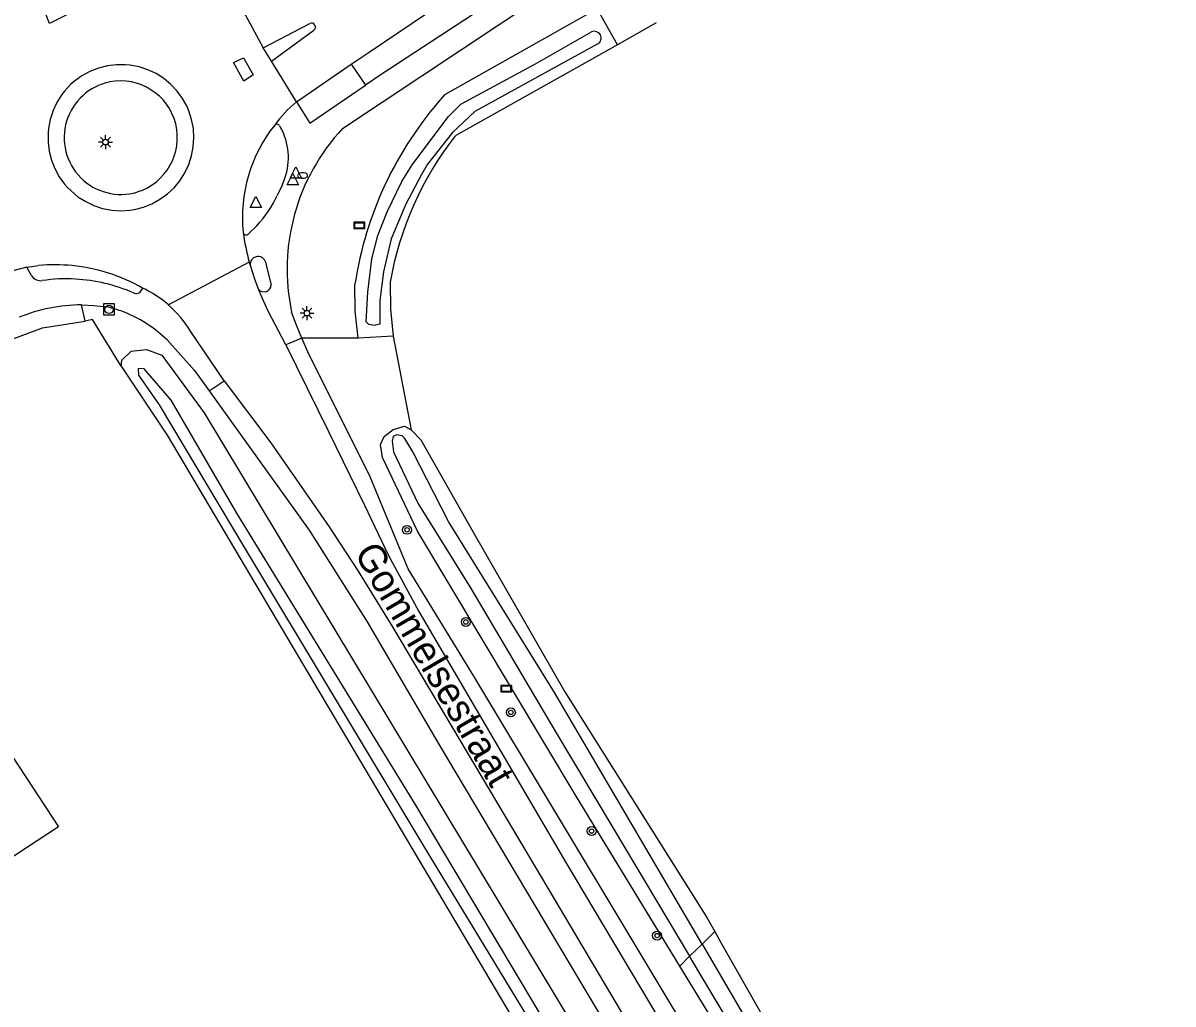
# Model space of a CAD drawing. Extents: x 137000 to 140001, y 403500 to 406000.
# Drawn here: x 139544.4 to 139647.6, y 403830.5 to 403918.5 of the extents above; entities that cross this region are included whole.
import ezdxf

# ---------------------------------------------------------------- set-up
doc = ezdxf.new("R2010")
doc.units = 0
for name, color, linetype in [('gg-anno-openbare ruimte label', 7, 'Continuous'), ('gg-bbg-hoofdgebouw', 7, 'Continuous'), ('gg-knt-bronhoudergrens', 7, 'Continuous'), ('gg-knt-verharding', 7, 'Continuous'), ('gg-knt-verharding nz', 7, 'Continuous'), ('gg-kntw-bovenkant insteek waterloop', 7, 'Continuous'), ('gg-kntw-waterlijn', 7, 'Continuous'), ('gt-grn-groengrens', 7, 'Continuous'), ('gt-grn-groengrens NZ', 7, 'Continuous'), ('gt-grn-vlakafsluiter', 7, 'Continuous'), ('gt-grn-weggrens', 7, 'Continuous'), ('gt-symb-boom', 7, 'Continuous'), ('gt-symb-brandkraan', 7, 'Continuous'), ('gt-symb-informatiebord', 7, 'Continuous'), ('gt-symb-lichtmast', 7, 'Continuous'), ('gt-symb-rioolschacht', 7, 'Continuous'), ('gt-symb-waterafsluiter', 7, 'Continuous')]:
    doc.layers.add(name, color=color, linetype=linetype)

# ---------------------------------------------------------------- blocks, each defined once
blk = doc.blocks.new('gt0-LMAST')
at = {"layer": 'gt-symb-lichtmast'}
for p, q in [((-0.18, 0.17), (-0.45, 0.44)), ((-0.01, 0.25), (-0.01, 0.62)), ((0.17, 0.17), (0.44, 0.44)), ((-0.26, 0), (-0.63, 0)), ((-0.18, -0.18), (-0.45, -0.45)), ((-0.01, -0.25), (-0.01, -0.63)), ((0.44, -0.45), (0.17, -0.18)), ((0.24, 0), (0.62, 0))]:
    blk.add_line(p, q, dxfattribs=at)
blk.add_circle((-0.01, 0), 0.25, dxfattribs=at)
blk = doc.blocks.new('gt0-WAFSL')
at = {"layer": 'gt-symb-waterafsluiter'}
for p, q in [((-0.5, -0.33), (0, 0.67)), ((0, 0.67), (0.5, -0.33)), ((0.5, -0.33), (-0.5, -0.33))]:
    blk.add_line(p, q, dxfattribs=at)
blk = doc.blocks.new('gt0-BR')
at = {"layer": 'gt-symb-brandkraan'}
for centre, radius, start, end in [((-0.24, 0), 0.206, 107.5669, 252.4331), ((0.6, -2.66), 3, 106.892, 107.5669), ((0, -0.69), 0.938, 73.108, 106.892), ((-0.6, -2.66), 3, 72.4331, 73.108), ((0.24, 0), 0.206, 287.567, 72.4331), ((0.6, 2.66), 3, 252.4331, 253.108), ((0, 0.69), 0.938, 253.108, 286.8921), ((-0.6, 2.66), 3, 286.8921, 287.567)]:
    blk.add_arc(centre, radius, start, end, dxfattribs=at)
blk = doc.blocks.new('gt0-IBORD')
at = {"layer": 'gt-symb-informatiebord'}
blk.add_lwpolyline([(-0.5, 0.29), (-0.5, -0.29), (0.5, -0.29), (0.5, 0.29), (-0.5, 0.29)], dxfattribs=at)
blk.add_lwpolyline([(-0.42, -0.21), (0.42, -0.21), (0.42, 0.21), (-0.42, 0.21)], close=True, dxfattribs=at)
blk = doc.blocks.new('gt0-RS')
at = {"layer": 'gt-symb-rioolschacht'}
blk.add_lwpolyline([(-0.5, -0.5), (0.5, -0.5), (0.5, 0.5), (-0.5, 0.5)], close=True, dxfattribs=at)
blk.add_circle((0, 0), 0.375, dxfattribs=at)
blk = doc.blocks.new('gt0-BOOM')
at = {"layer": 'gt-symb-boom'}
for radius in [0.4, 0.2]:
    blk.add_circle((0, 0), radius, dxfattribs=at)

msp = doc.modelspace()

# ---------------------------------------------------------------- linework, layer by layer
at = {"layer": 'gg-bbg-hoofdgebouw'}
msp.add_lwpolyline([(139526.12, 403841.26), (139543.52, 403852.68), (139547.62, 403846.42), (139530.21, 403835), (139526.12, 403841.26)], dxfattribs=at)
at = {"layer": 'gg-knt-bronhoudergrens'}
for p, q in [((139601.24, 403918.51), (139597.76, 403916.55)), ((139577.65, 403890.41), (139579.26, 403882.02))]:
    msp.add_line(p, q, dxfattribs=at)
msp.add_lwpolyline([(139553.26, 403887.72), (139550.69, 403891.91), (139550.03, 403891.77)], dxfattribs=at)
at = {"layer": 'gg-knt-verharding'}
for p, q in [((139573.1, 403909.05), (139593.34, 403922.49)), ((139565.99, 403916.28), (139570.17, 403918.45)), ((139566.73, 403915.07), (139570.54, 403917.85)), ((139566.73, 403915.07), (139565.99, 403916.28)), ((139568.97, 403911.43), (139573.88, 403914.8)), ((139573.88, 403914.8), (139575.17, 403912.92)), ((139567.46, 403909.27), (139567.8, 403908.62)), ((139567.71, 403904.03), (139567.24, 403903.04)), ((139565.41, 403900.32), (139564.68, 403899.59)), ((139544.78, 403896.6), (139542.84, 403896.1)), ((139544.78, 403896.6), (139545.85, 403896.76)), ((139545.19, 403895.88), (139544.78, 403896.6)), ((139564.81, 403896.83), (139564.74, 403897.06)), ((139566.17, 403897.15), (139566.7, 403895.02)), ((139555.16, 403894.73), (139555.05, 403894.54)), ((139557.48, 403893.24), (139556.98, 403893.64)), ((139562.49, 403886.42), (139559.48, 403890.86)), ((139569.44, 403890.24), (139568.03, 403889.64)), ((139561.15, 403885.51), (139562.49, 403886.42))]:
    msp.add_line(p, q, dxfattribs=at)
for points in [[(139573.88, 403914.8), (139575.41, 403915.81), (139580.71, 403919.42), (139587.97, 403924.39)], [(139589.33, 403922.26), (139576.58, 403913.87), (139575.17, 403912.92)], [(139546.81, 403918.45), (139546.44, 403919.43), (139548.14, 403920.23), (139548.62, 403919.36), (139546.81, 403918.45)], [(139564.25, 403913.27), (139563.33, 403914.95), (139564.23, 403915.39), (139565.08, 403913.84), (139564.25, 403913.27)], [(139559.72, 403907.39), (139559.78, 403908.21), (139559.73, 403909.03), (139559.57, 403909.84), (139559.32, 403910.62), (139559.16, 403911), (139558.76, 403911.72), (139558.28, 403912.39), (139557.71, 403912.99), (139557.08, 403913.52), (139556.39, 403913.96), (139555.64, 403914.31), (139554.86, 403914.56), (139554.05, 403914.72), (139553.64, 403914.76), (139552.82, 403914.76), (139552.01, 403914.66), (139551.21, 403914.45), (139550.44, 403914.15), (139549.72, 403913.75), (139549.06, 403913.27), (139548.75, 403913), (139548.18, 403912.4), (139547.93, 403912.08), (139547.49, 403911.38), (139547.14, 403910.64), (139546.88, 403909.86), (139546.73, 403909.05), (139546.69, 403908.64), (139546.69, 403907.82), (139546.79, 403907), (139546.99, 403906.2), (139547.3, 403905.44), (139547.69, 403904.72), (139548.18, 403904.05), (139548.45, 403903.74), (139549.05, 403903.18), (139549.37, 403902.92), (139550.07, 403902.48), (139550.81, 403902.13), (139551.59, 403901.88), (139552.4, 403901.72), (139553.22, 403901.67), (139554.04, 403901.72), (139554.45, 403901.78), (139555.24, 403901.99), (139556.01, 403902.29), (139556.73, 403902.69), (139557.4, 403903.17), (139558, 403903.73), (139558.52, 403904.36), (139558.96, 403905.06), (139559.31, 403905.8), (139559.57, 403906.58), (139559.72, 403907.39)], [(139568.97, 403911.43), (139570.17, 403909.52), (139575.17, 403912.92)], [(139565.57, 403894.64), (139565.23, 403895.54), (139564.81, 403896.83)], [(139568.03, 403889.64), (139566.43, 403892.67), (139565.9, 403893.87), (139565.57, 403894.64)], [(139549.69, 403893.22), (139550.81, 403893.18), (139551.92, 403893.06)], [(139569.44, 403890.24), (139568.96, 403891.4), (139568.53, 403892.57)], [(139557.37, 403890.08), (139559.84, 403887.35), (139561.15, 403885.51)], [(139620.78, 403800.15), (139584.89, 403859.93), (139578.98, 403869.55), (139575.57, 403877.81), (139570, 403889), (139569.44, 403890.24)], [(139561.15, 403885.51), (139570.1, 403873.01), (139575.32, 403864.8), (139581.78, 403853.77), (139598.92, 403824.97)]]:
    msp.add_lwpolyline(points, dxfattribs=at)
for centre, radius, start, end in [((139570.33, 403918.13), 0.356, 306.2061, 117.411), ((139576.32, 403902.6), 11.49, 129.7937, 144.0208), ((139577.43, 403901.06), 13.31, 141.46, 185.766), ((139567.2, 403909.12), 0.299, 32.0354, 127.9785), ((139586.69, 403896.4), 18.56, 137.0524, 191.932), ((139562.7, 403906.43), 5.55, 334.4209, 23.2571), ((139557.61, 403907.55), 10.64, 317.1854, 334.9408), ((139582.91, 403902.19), 18.88, 187.4941, 195.7537), ((139564.47, 403899.79), 0.289, 194.0032, 316.0027), ((139565.52, 403896.85), 0.716, 25.2765, 181.3076), ((139547.27, 403880.83), 15.99, 84.2936, 95.0973), ((139547.27, 403880.84), 15.98, 60.3948, 84.275), ((139546.05, 403896.39), 0.999, 210.454, 277.1621), ((139548.35, 403880.27), 15.29, 87.0147, 98.1851), ((139548.33, 403880.35), 15.2, 66.6532, 86.9454), ((139554.61, 403894.73), 0.487, 239.4656, 337.1076), ((139551.04, 403885.82), 9.82, 52.7717, 65.1898), ((139566.07, 403895.01), 0.624, 217.2991, 0.5188), ((139549.73, 403878.28), 14.94, 90.1669, 112.1132), ((139549.41, 403881.96), 11.38, 67.4954, 77.2786), ((139549.44, 403882.06), 11.27, 45.3365, 67.4524), ((139551.02, 403885.78), 9.86, 30.9588, 49.1051)]:
    msp.add_arc(centre, radius, start, end, dxfattribs=at)
at = {"layer": 'gg-knt-verharding nz'}
for points in [[(139568.03, 403889.64), (139571.85, 403881.88), (139575.08, 403875.25), (139577.18, 403870.82), (139579.94, 403865.74), (139593.13, 403843.22), (139606.51, 403820.75), (139634.96, 403773.42), (139647.99, 403751.99), (139661.28, 403730.67), (139675.19, 403708.59), (139689.23, 403686.58), (139702.91, 403665.56), (139731.61, 403621.93), (139759.26, 403580.01), (139787.35, 403537.2), (139801.42, 403515.21), (139811.03, 403500)], [(139562.49, 403886.42), (139566.67, 403880.85), (139571.89, 403873.33), (139574.49, 403869.35), (139577.61, 403864.3), (139590.95, 403841.87), (139604.28, 403819.39), (139617.16, 403797.87), (139632.68, 403772.16), (139646.25, 403749.84), (139659.52, 403728.52), (139672.94, 403707.28), (139686.99, 403685.26), (139701.23, 403663.38), (139729.36, 403620.55), (139757.47, 403577.82), (139785.09, 403535.88), (139798.6, 403514.72), (139807.89, 403500)]]:
    msp.add_lwpolyline(points, dxfattribs=at)
at = {"layer": 'gg-kntw-bovenkant insteek waterloop'}
for p, q in [((139597.76, 403916.55), (139583.25, 403908.42)), ((139577.65, 403890.41), (139574.49, 403890.25)), ((139606.48, 403837.03), (139607.04, 403836.06))]:
    msp.add_line(p, q, dxfattribs=at)
for points in [[(139597.76, 403916.55), (139595.95, 403919.77), (139582.26, 403912.05), (139582.08, 403911.85)], [(139574.49, 403890.25), (139574.24, 403892.66), (139574.22, 403895.09)], [(139577.38, 403895.25), (139577.4, 403892.83), (139577.65, 403890.41)], [(139553.26, 403887.72), (139553.32, 403888.26), (139554.14, 403889.06), (139555.52, 403889.22), (139556.89, 403888.72), (139560.68, 403883.53), (139593.91, 403828.4)], [(139553.26, 403887.72), (139557.38, 403881.54), (139590.52, 403825.58)], [(139603.35, 403833.94), (139594.06, 403849.17), (139579.84, 403872.92), (139576.69, 403879.55), (139576.5, 403880.69), (139576.83, 403881.42), (139577.65, 403882.06), (139578.67, 403882.35), (139579.26, 403882.02)], [(139579.26, 403882.02), (139580.12, 403881.13), (139584.8, 403872.89), (139593.05, 403858.53), (139605.77, 403838.29), (139606.48, 403837.03)], [(139607.04, 403836.06), (139620.83, 403811.74), (139623.64, 403806.48), (139624.61, 403804.59), (139624.95, 403803.89)], [(139622.86, 403802.25), (139622.07, 403803.65), (139621.33, 403804.35), (139619.81, 403807.06), (139608.91, 403824.83), (139603.35, 403833.94)]]:
    msp.add_lwpolyline(points, dxfattribs=at)
for radius, start, end in [(32.55, 138.349, 171.3838), (29.46, 141.8068, 170.1464)]:
    msp.add_arc((139606.4, 403890.21), radius, start, end, dxfattribs=at)
at = {"layer": 'gg-kntw-waterlijn'}
for p, q in [((139605.34, 403835.91), (139624.2, 403803.72)), ((139623.24, 403803.02), (139604.23, 403834.81))]:
    msp.add_line(p, q, dxfattribs=at)
for points in [[(139595.99, 403916.62), (139584.98, 403910.57), (139582.96, 403908.69), (139580.73, 403905.84), (139580.15, 403904.85), (139578.78, 403902.24), (139577.47, 403899.14), (139576.78, 403896.2), (139576.44, 403893.62), (139576.44, 403891.5), (139575.95, 403891.37), (139575.47, 403891.45), (139575.22, 403891.71), (139575.38, 403894.35), (139575.73, 403897.36), (139576.26, 403899.45), (139577.1, 403901.57), (139578.42, 403904.28), (139579.34, 403905.79), (139582.62, 403910.12), (139583.7, 403911.21), (139590.42, 403914.84), (139595.44, 403917.7)], [(139592.41, 403826.99), (139579.67, 403848.35), (139563.63, 403874.55), (139557.74, 403884.67), (139555.3, 403887.48), (139554.78, 403887.53), (139554.81, 403886.92), (139556.65, 403884.27), (139564.21, 403871.6), (139580.48, 403844.51), (139590.61, 403827.84)], [(139605.34, 403835.91), (139592.12, 403858.48), (139582.62, 403873.8), (139579.4, 403880.05), (139578.68, 403881.25), (139578.45, 403881.47), (139577.95, 403881.58), (139577.65, 403881.41), (139577.55, 403880.99), (139577.68, 403880.04), (139579.87, 403875.44), (139584.58, 403867.86), (139592.17, 403855), (139597.37, 403846.29), (139604.23, 403834.81)]]:
    msp.add_lwpolyline(points, dxfattribs=at)
msp.add_arc((139595.69, 403917.15), 0.606, 300.0943, 114.0948, dxfattribs=at)
at = {"layer": 'gt-grn-groengrens'}
msp.add_line((139574.49, 403890.25), (139569.44, 403890.24), dxfattribs=at)
msp.add_lwpolyline([(139541.91, 403889.45), (139543.16, 403890.03), (139546.19, 403891.18), (139550.03, 403891.77)], dxfattribs=at)
at = {"layer": 'gt-grn-groengrens NZ'}
msp.add_line((139550.03, 403891.77), (139549.69, 403893.22), dxfattribs=at)
for centre, start, end in [((139553.23, 403908.22), 101.5101, 286.5597), ((139553.2, 403908.22), 286.8477, 101.222)]:
    msp.add_arc(centre, 5.09, start, end, dxfattribs=at)
at = {"layer": 'gt-grn-vlakafsluiter'}
for p, q in [((139606.48, 403837.03), (139605.34, 403835.91)), ((139605.34, 403835.91), (139604.23, 403834.81)), ((139603.35, 403833.94), (139604.23, 403834.81))]:
    msp.add_line(p, q, dxfattribs=at)
at = {"layer": 'gt-grn-weggrens'}
for p, q in [((139564.23, 403919.54), (139565.99, 403916.28)), ((139568.97, 403911.43), (139566.73, 403915.07)), ((139564.74, 403897.06), (139557.48, 403893.24))]:
    msp.add_line(p, q, dxfattribs=at)

# ---------------------------------------------------------------- block references
at = {"layer": 'gt-symb-boom'}
for p in [(139578.89, 403873.05), (139584.16, 403864.79), (139588.2, 403856.68), (139595.44, 403846.04), (139601.31, 403836.67)]:
    msp.add_blockref('gt0-BOOM', p, dxfattribs=at)
at = {"layer": 'gt-symb-brandkraan'}
msp.add_blockref('gt0-BR', (139569.52, 403904.83), dxfattribs=at)
at = {"layer": 'gt-symb-informatiebord'}
for p in [(139574.61, 403900.35), (139587.79, 403858.81)]:
    msp.add_blockref('gt0-IBORD', p, dxfattribs=at)
at = {"layer": 'gt-symb-lichtmast'}
for p in [(139551.85, 403907.82), (139569.92, 403892.48)]:
    msp.add_blockref('gt0-LMAST', p, dxfattribs=at)
at = {"layer": 'gt-symb-rioolschacht'}
msp.add_blockref('gt0-RS', (139552.16, 403892.82), dxfattribs=at)
at = {"layer": 'gt-symb-waterafsluiter'}
for p in [(139568.64, 403904.33), (139568.91, 403904.93), (139565.33, 403902.28)]:
    msp.add_blockref('gt0-WAFSL', p, dxfattribs=at)

# ---------------------------------------------------------------- texts
at = {"layer": 'gg-anno-openbare ruimte label'}
msp.add_text('Gommelsestraat', height=2.5, rotation=300.3, dxfattribs=at).set_placement((139574.1, 403870.98))

doc.saveas('drawing.dxf')
